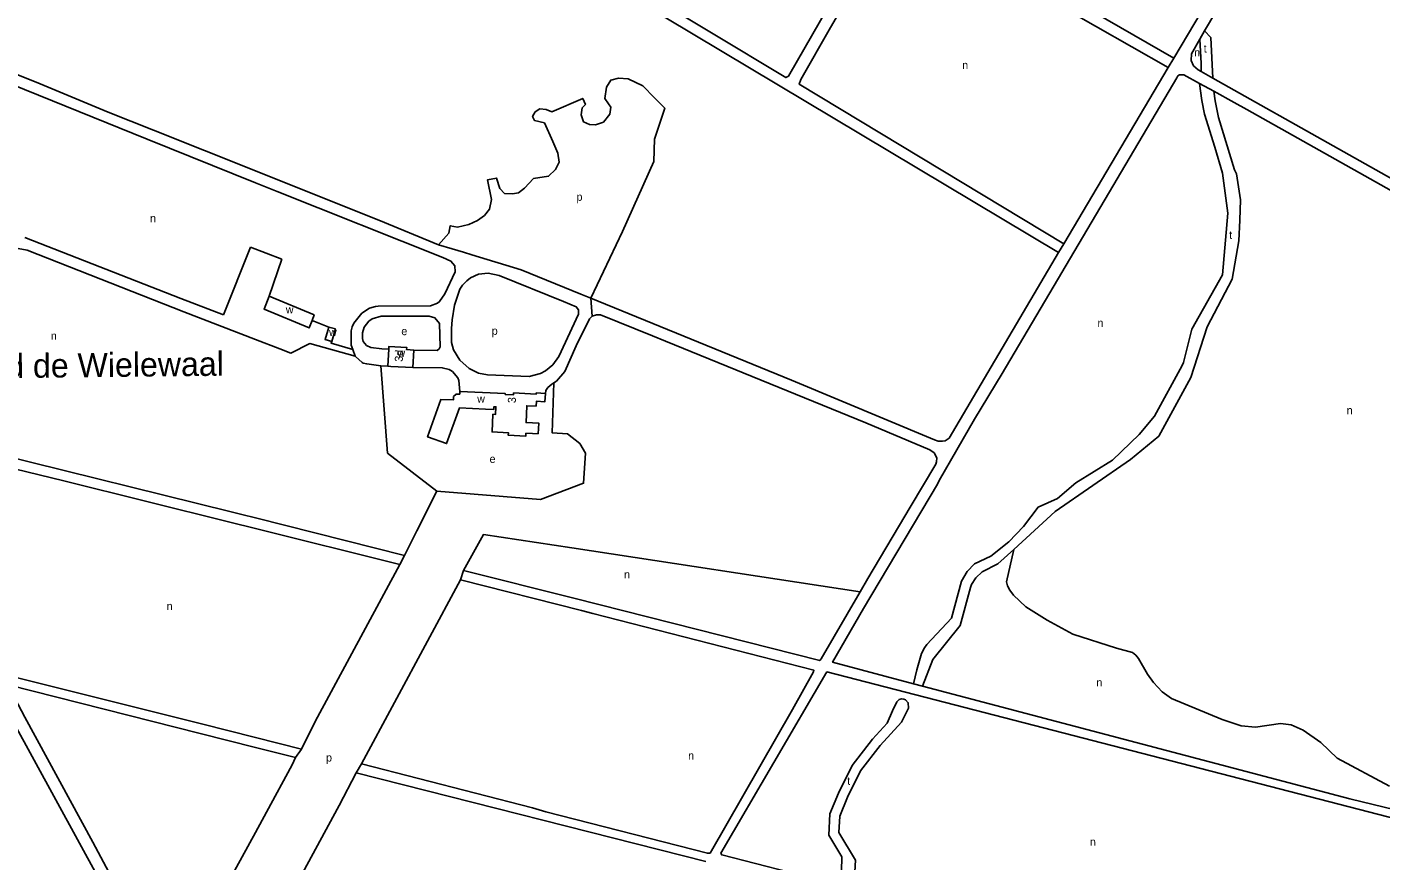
# Model space of a CAD drawing. Extents: x 156521 to 159067, y 384230 to 386095.
# Drawn here: x 157936 to 158613, y 384783 to 385200 of the extents above; entities that cross this region are included whole.
import ezdxf

# ---------------------------------------------------------------- set-up
doc = ezdxf.new("R2010")
doc.units = 0
for name, color, linetype in [('BLT_Basislijn', 7, 'Continuous'), ('BLT_Bebouwing', 7, 'Continuous'), ('BLT_Centroide', 7, 'Continuous'), ('BLT_Huisnummer', 7, 'Continuous'), ('BLT_Sport_parknaam', 7, 'Continuous'), ('BLT_Vlakafsluiter', 7, 'Continuous')]:
    doc.layers.add(name, color=color, linetype=linetype)

msp = doc.modelspace()

# ---------------------------------------------------------------- linework, layer by layer
at = {"layer": 'BLT_Basislijn'}
for p, q in [((158522.1, 385194.19), (158524.55, 385198.42)), ((158509.19, 385184.74), (158506.33, 385179.97)), ((158454.18, 385091.87), (158506.33, 385179.97)), ((158522.78, 385177.99), (158528.66, 385174.61)), ((158521.94, 385172.02), (158529.18, 385168.2)), ((158539.39, 385162.51), (158529.18, 385168.2)), ((158034.03, 385056.38), (158047.49, 385090.13)), ((158047.49, 385090.13), (158063.22, 385084.15)), ((158148.42, 385089.36), (158141.58, 385091.37)), ((158154.01, 385087.61), (158148.42, 385089.36)), ((158454.18, 385091.87), (158451.58, 385087.55)), ((158063.22, 385084.15), (158056.81, 385065.74)), ((158154.01, 385087.61), (158158.2, 385086.34)), ((158012.65, 385064.54), (158034.03, 385056.38)), ((158212.75, 385066.62), (158217.64, 385064.67)), ((158078.31, 385053.48), (158086.67, 385050.25)), ((158098.71, 385038.98), (158099.91, 385035.72)), ((158113.23, 385039.37), (158116.63, 385039.17)), ((158112.74, 385030.84), (158116.14, 385030.64)), ((157852.35, 385003.63), (158037.88, 384957.79)), ((158037.88, 384957.79), (158043.15, 384956.48)), ((158050, 384954.76), (158043.15, 384956.48)), ((158124.62, 384936.05), (158050, 384954.76)), ((158122.2, 384931.55), (158050, 384949.5)), ((158122.2, 384931.55), (158124.62, 384936.05)), ((158154.07, 384928.52), (158152.46, 384923.86)), ((158209.27, 384914.6), (158154.07, 384928.52)), ((158152.46, 384923.86), (158103.09, 384831.78)), ((158152.46, 384923.86), (158213.1, 384908.5)), ((157924.31, 384876.54), (158022.99, 384851.73)), ((158383.51, 384870.65), (158379.02, 384871.85)), ((158022.99, 384851.73), (158050, 384844.94)), ((158050, 384844.94), (158073, 384839.16)), ((158050, 384840.02), (158070.12, 384834.92)), ((158070.12, 384834.92), (158073, 384839.16)), ((158103.09, 384831.78), (158100.39, 384827.29)), ((158188.54, 384809.83), (158103.09, 384831.78)), ((158100.39, 384827.29), (158275.16, 384782.89))]:
    msp.add_line(p, q, dxfattribs=at)
for points in [[(158182.12, 385374.2), (158291.65, 385310.46), (158371.52, 385264.04), (158509.19, 385184.74)], [(157976.34, 385157.64), (157942.43, 385171.89), (157884.65, 385195.02), (157881.29, 385197.34), (157879.08, 385199.55), (157877.9, 385202.27), (157877.79, 385205.87), (157879.29, 385210.09), (157933.78, 385294.51), (157934.28, 385295.7), (157981.19, 385369.95)], [(158549.58, 385278.11), (158551.86, 385261.78), (158551.57, 385256.78), (158551.09, 385255.51), (158509.19, 385184.74)], [(158524.55, 385198.42), (158554.77, 385249.34), (158558.89, 385253.82), (158563, 385256.41), (158566.95, 385258.07), (158588.51, 385261.81)], [(158454.18, 385091.87), (158321.77, 385171.77), (158322.73, 385173.94), (158337.59, 385199.98), (158370.85, 385257.22), (158379.91, 385252.58), (158433.65, 385221.48), (158506.33, 385179.97)], [(158203.7, 385242.18), (158315.18, 385175.02), (158316.51, 385175.77), (158336.27, 385210.21), (158342.84, 385221.87)], [(158451.58, 385087.55), (158212.45, 385230.51), (158202.32, 385236.66)], [(158528.66, 385174.61), (158527.61, 385194.95), (158524.55, 385198.42)], [(157831.84, 385134.63), (157861.46, 385181.39), (157866.33, 385188.34), (157869.88, 385190.77), (157872.04, 385191.4), (157876.54, 385191.85), (157880.01, 385191.02), (157995.96, 385144.13)], [(158522.1, 385194.19), (158517.98, 385186.9), (158517.82, 385183.49), (158519.08, 385180.87), (158521.36, 385178.8), (158522.78, 385177.99)], [(158522.1, 385194.19), (158522.85, 385182), (158522.78, 385177.99)], [(158141.58, 385091.37), (158146.67, 385097.18), (158147.38, 385100.91), (158151.11, 385100.19), (158156.65, 385101.54), (158161.06, 385103.45), (158164.46, 385106.03), (158167.04, 385109.13), (158168.05, 385114.07), (158166.11, 385123.87), (158170.61, 385124.76), (158172.27, 385119.53), (158174.55, 385117.06), (158178.47, 385116.84), (158181.57, 385117.4), (158184.49, 385119.64), (158189.05, 385124.46), (158196.56, 385125.61), (158200, 385128.97), (158201.87, 385132.6), (158201.27, 385137.2), (158198.62, 385143.1), (158194.49, 385152.29), (158189.57, 385153.5), (158188.56, 385155.52), (158189.83, 385157.8), (158192.26, 385159.41), (158195.32, 385159.07), (158198.12, 385157.8), (158213.67, 385164.56), (158215.01, 385161.5), (158213.34, 385159.85), (158212.89, 385156.42), (158214.05, 385152.9), (158217.07, 385151.56), (158220.1, 385151.41), (158223.95, 385152.68), (158227.16, 385156.67), (158227.72, 385160.19), (158226.56, 385161.83), (158224.73, 385164.44), (158225.59, 385170.13), (158227.75, 385173.73), (158231.47, 385174.71), (158236.31, 385174.38), (158243.63, 385170.85), (158249.52, 385164.9), (158254.63, 385159.73), (158249.5, 385144.19), (158249.24, 385132.94), (158233.53, 385098.01), (158217.64, 385064.67)], [(158521.94, 385172.02), (158514.16, 385176.39), (158512, 385176.39), (158511.18, 385175.79), (158510.6, 385174.89), (158423.37, 385027.06), (158409.56, 385004.11), (158391.81, 384973.56), (158390.96, 384971.68), (158354.04, 384909.41), (158338.53, 384882.65), (158379.02, 384871.85)], [(158521.94, 385172.02), (158523.15, 385163.55), (158524.51, 385156.68), (158529.74, 385140.21), (158533.42, 385127.14), (158536.18, 385107.11), (158533.42, 385076.42), (158518.14, 385049.14), (158514.07, 385032.58), (158513.4, 385030.92), (158499.49, 385005.64), (158491.83, 384996.53), (158478.44, 384983.62), (158460.1, 384972.35), (158451.06, 384964.55), (158441.32, 384960.12), (158433.93, 384950.54), (158426.68, 384942.9), (158417.7, 384935.58), (158409.58, 384931.78), (158405.85, 384928.03), (158403.05, 384923.07), (158397.96, 384904.62), (158385.72, 384891.51), (158384.5, 384889.88), (158383.06, 384887.03), (158380.64, 384878.87), (158379.02, 384871.85)], [(158528.66, 385174.61), (158654.35, 385103.98), (158711.3, 385071.58), (158715.21, 385069.61), (158765.14, 385040.3)], [(158540.53, 385126.81), (158539.56, 385128.87), (158531.51, 385155), (158529.83, 385163.43), (158529.18, 385168.2)], [(158050, 385128.33), (157999.1, 385148.7), (157976.34, 385157.64)], [(158539.39, 385162.51), (158545.74, 385158.98), (158651.48, 385099.52), (158683.59, 385080.92)], [(157995.96, 385144.13), (158050, 385122.29)], [(158066.21, 385121.84), (158050, 385128.33)], [(158540.53, 385126.81), (158542.54, 385113.77), (158542.14, 385103.72), (158541.65, 385093.39), (158538.36, 385074.23), (158525.83, 385050.35), (158517.67, 385024.94), (158501.72, 384995.72), (158487.57, 384983.96), (158449.92, 384957.93), (158429.1, 384938.99)], [(158050, 385122.29), (158060.9, 385117.95)], [(158060.9, 385117.95), (158143.68, 385085.05), (158147.77, 385083.13), (158149.63, 385080.82), (158149.79, 385077.89), (158144.7, 385066.81), (158142.09, 385062.99), (158141.05, 385062.11), (158137.6, 385060.92), (158111.41, 385060.68), (158110.06, 385060.44), (158106.97, 385059.65), (158103.14, 385057.15), (158099.29, 385052.09)], [(158141.58, 385091.37), (158111.78, 385103.6), (158066.21, 385121.84)], [(157812.16, 385103.68), (157877.05, 385099.58), (157935.85, 385088.63)], [(157934.68, 385094.95), (158012.65, 385064.54)], [(157935.85, 385088.63), (158014.22, 385057.9)], [(158158.2, 385086.34), (158182.9, 385078.84), (158212.75, 385066.62)], [(158217.64, 385064.67), (158318.04, 385023.68), (158389.58, 384993.77), (158391.27, 384993.11), (158393.57, 384993.17), (158394.77, 384993.33), (158396.78, 384994.7), (158451.58, 385087.55)], [(158203.95, 385063.03), (158210.44, 385060.28), (158211.49, 385058.79), (158211.5, 385056.7), (158201.68, 385035.44), (158198.66, 385031.31), (158194.96, 385028.29), (158192.61, 385026.95), (158186.82, 385025.58), (158165.96, 385026.38), (158161.48, 385027.17), (158156.84, 385029.48), (158152.13, 385033.64), (158148.99, 385038.89), (158148.07, 385042.57), (158148.04, 385049.46), (158148.43, 385053.83), (158149.58, 385061.13), (158152.18, 385069.13), (158153.61, 385071.2), (158155.68, 385073.41), (158157.52, 385074.79), (158161.57, 385076.73), (158166.35, 385077.24), (158171.92, 385075.98), (158203.95, 385063.03)], [(158014.22, 385057.9), (158050, 385044.01)], [(158129.25, 385038.72), (158140.82, 385038.43), (158141.81, 385039.38), (158142.31, 385040.38), (158141.99, 385052), (158139.76, 385054.76), (158136.9, 385055.59), (158112.86, 385055.59), (158108.31, 385054.33), (158106.72, 385053.12), (158104.42, 385050.19), (158103.51, 385047.42), (158103.51, 385044.46), (158103.95, 385042.92), (158105.6, 385040.93), (158107.77, 385040.07), (158113.23, 385039.37)], [(158199.28, 385022.35), (158200.51, 385023.19), (158204.71, 385027.96), (158210.29, 385040.84), (158216.97, 385054.39), (158218.34, 385055.73)], [(158218.34, 385055.73), (158220.53, 385056.28), (158222.54, 385056.3), (158248.53, 385045.78), (158254.98, 385043.14), (158355.12, 385002.33), (158387.23, 384988.9), (158389.3, 384987.4), (158390.73, 384984.77), (158390.55, 384982.84), (158390.13, 384981.63), (158377.39, 384960.15), (158374.72, 384955.66), (158356.25, 384924.52), (158352.4, 384917.74)], [(158099.29, 385052.09), (158098.39, 385050.39), (158097.85, 385048.28), (158097.9, 385041.18), (158098.71, 385038.98)], [(158050, 385044.01), (158062.29, 385039.28)], [(158062.29, 385039.28), (158067.72, 385037.1), (158077.13, 385041.96), (158099.91, 385035.72)], [(158088.14, 385043.06), (158087.87, 385042.14), (158098.71, 385038.98)], [(158099.91, 385035.72), (158100.01, 385035.46), (158103.35, 385032.43), (158103.95, 385032.19)], [(158103.95, 385032.19), (158105.63, 385031.81), (158112.74, 385030.84)], [(158140.74, 384968.09), (158116.03, 384987.18), (158112.74, 385030.84)], [(158152.23, 385017.97), (158151.7, 385023.51), (158151.22, 385024.78), (158148.52, 385028.04), (158146.9, 385028.97), (158143.43, 385029.89), (158128.75, 385030.06)], [(158140.74, 384968.09), (158192.58, 384963.99), (158214.11, 384972.11), (158215.11, 384987.15), (158212.12, 384991.97), (158206.06, 384996.76), (158198.35, 384997.33), (158198.54, 385002.41), (158199.28, 385022.35)], [(158199.28, 385022.35), (158198.15, 385021.75), (158196.22, 385020.05), (158195.18, 385018.56), (158194.97, 385017.04)], [(158037.16, 384952.69), (157954.15, 384973.32), (157856.66, 384997.07)], [(158124.62, 384936.05), (158130.75, 384948.31), (158140.74, 384968.09)], [(158050, 384949.5), (158037.16, 384952.69)], [(158352.4, 384917.74), (158208.13, 384939.84), (158164.03, 384946.46), (158154.07, 384928.52)], [(158429.1, 384938.99), (158421.21, 384931.81), (158413.4, 384927.74), (158410.22, 384924.82), (158408.08, 384921.54), (158407.45, 384919.95), (158402.42, 384901.03), (158388.61, 384884.03), (158383.51, 384870.65)], [(158616.96, 384820.59), (158590.84, 384834.71), (158582.67, 384842.46), (158573.84, 384848.58), (158567.75, 384851.26), (158562.46, 384851.9), (158550.04, 384850.21), (158542.81, 384850.88), (158533.25, 384854.01), (158507.99, 384864.54), (158503.35, 384867.76), (158499.07, 384872.55), (158496.03, 384876.62), (158491.57, 384884.43), (158490.12, 384886.18), (158488.44, 384887.48), (158480.5, 384889.63), (158458.64, 384896.61), (158445.81, 384903.57), (158435.16, 384910.27), (158429, 384916.2), (158427.21, 384918.64), (158425.97, 384920.74), (158425.44, 384922.74), (158429.1, 384938.99)], [(158073, 384839.16), (158079.95, 384852.93), (158122.2, 384931.55)], [(158352.4, 384917.74), (158332.87, 384884.25), (158332.15, 384883.46), (158209.27, 384914.6)], [(158188.54, 384809.83), (158195.14, 384807.87), (158276.02, 384787.12), (158277.3, 384787.09), (158318.58, 384859.01), (158329.03, 384877.79), (158329.19, 384878.59), (158218.67, 384906.96), (158213.1, 384908.5)], [(157995.65, 384730.34), (157982.71, 384754.25), (157917.51, 384873.23), (157868.18, 384885.68), (157845.99, 384890.93)], [(158342.81, 384770.73), (158333.64, 384773.36), (158283.17, 384786.22), (158282.77, 384787.06), (158335.72, 384877.79), (158631, 384801.39), (158631.05, 384800.83), (158627.73, 384794.49), (158603.23, 384753.88), (158602.28, 384751.89), (158580.79, 384715.97), (158576.88, 384709.55), (158576.56, 384709.5), (158462.13, 384739.64), (158349.17, 384768.98)], [(158000.94, 384733.19), (157997.78, 384738.29), (157968.8, 384792.69), (157934.68, 384855.1), (157926.36, 384870.92), (157926.44, 384871.29), (158022.33, 384847.02)], [(158625.27, 384807.42), (158597.16, 384814.34), (158383.51, 384870.65)], [(158365.9, 384852.2), (158368.52, 384858.35), (158370.73, 384862.8), (158371.79, 384863.91), (158373.06, 384864.28), (158374.25, 384864.19), (158374.99, 384863.89), (158376.37, 384862.32), (158376.47, 384859.71), (158373.09, 384852.64)], [(158365.9, 384852.2), (158358.55, 384844.17), (158348.33, 384831.03), (158341.47, 384817.14), (158337.14, 384806.78), (158336.69, 384796.16), (158343.14, 384785.29)], [(158373.09, 384852.64), (158362.37, 384840.94), (158352.58, 384828.36), (158346.02, 384815.07), (158342.1, 384805.67), (158341.75, 384797.43), (158349.95, 384783.61)], [(158022.33, 384847.02), (158050, 384840.02)], [(158017.25, 384735.99), (158018.55, 384739.35), (158026.59, 384754.11), (158027.24, 384755.78), (158050, 384797.52), (158055.51, 384807.62), (158068.42, 384831.28), (158070.12, 384834.92)], [(158100.39, 384827.29), (158091.95, 384810.99), (158066.98, 384765.07), (158050, 384733.85), (158043.28, 384721.5)], [(158342.81, 384770.73), (158343.14, 384785.29)], [(158349.95, 384783.61), (158349.17, 384768.98)]]:
    msp.add_lwpolyline(points, dxfattribs=at)
at = {"layer": 'BLT_Bebouwing'}
for p, q in [((158116.63, 385039.17), (158116.14, 385030.64)), ((158128.75, 385030.06), (158129.25, 385038.72)), ((158188.55, 384997.01), (158185.27, 384997.16)), ((158191.42, 384996.88), (158188.55, 384997.01))]:
    msp.add_line(p, q, dxfattribs=at)
for points in [[(158056.81, 385065.74), (158054.33, 385059.22), (158076.88, 385049.78), (158078.31, 385053.48)], [(158078.31, 385053.48), (158079.36, 385056.3), (158056.81, 385065.74)], [(158086.67, 385050.25), (158084.85, 385044.03), (158088.14, 385043.06)], [(158088.14, 385043.06), (158089.96, 385049.28), (158086.67, 385050.25)], [(158129.25, 385038.72), (158125.61, 385038.93), (158125.68, 385040.02), (158116.71, 385040.53), (158116.63, 385039.17)], [(158116.14, 385030.64), (158117.66, 385030.55), (158128.75, 385030.06)], [(158150.4, 385016.74), (158149.05, 385015.48), (158148.97, 385013.78), (158142.71, 385014.04), (158136.07, 384995.32), (158145.57, 384991.92), (158151.97, 385009.79), (158164.97, 385009.2), (158169.21, 385009.08), (158169.27, 385010.38), (158170.27, 385010.34), (158170.1, 385006.53), (158168.73, 385006.59), (158168.32, 384997.76), (158176.46, 384997.39), (158176.4, 384996.11), (158185.21, 384995.71), (158185.27, 384997.16)], [(158152.23, 385017.97), (158152.15, 385016.68), (158150.4, 385016.74)], [(158179, 385017.25), (158178.96, 385016.32), (158174.88, 385016.54), (158174.9, 385016.94), (158174.9, 385016.94), (158152.23, 385017.97)], [(158194.97, 385017.04), (158190.41, 385017.25), (158190.4, 385016.71), (158179, 385017.25)], [(158194.97, 385017.04), (158194.78, 385012.9), (158190.51, 385013.09), (158190.4, 385010.69)], [(158190.4, 385010.69), (158185.67, 385010.9), (158185.29, 385002.48), (158191.66, 385002.19), (158191.42, 384996.88)]]:
    msp.add_lwpolyline(points, dxfattribs=at)
at = {"layer": 'BLT_Vlakafsluiter'}
msp.add_line((158217.64, 385064.67), (158218.34, 385055.73), dxfattribs=at)

# ---------------------------------------------------------------- texts
at = {"layer": 'BLT_Centroide'}
for s, p in [('t', (158524.09, 385187.5)), ('n', (158519.33, 385185.56)), ('n', (158403.37, 385179.25)), ('p', (158210.53, 385113.35)), ('n', (157997.32, 385102.65)), ('t', (158536.82, 385094.3)), ('w', (158065.19, 385057.02)), ('w', (158086.8, 385045.76)), ('e', (158122.95, 385046.18)), ('p', (158168.16, 385046.34)), ('n', (158470.99, 385050.29)), ('n', (157947.72, 385043.85)), ('w', (158121.02, 385035.31)), ('w', (158160.88, 385012.39)), ('n', (158595.6, 385006.6)), ('e', (158167.07, 384982.29)), ('n', (158234.32, 384924.5)), ('n', (158005.63, 384908.7)), ('n', (158470.43, 384870.52)), ('p', (158085.32, 384832.95)), ('n', (158266.34, 384833.93)), ('t', (158345.89, 384821.29)), ('n', (158467.21, 384790.82))]:
    msp.add_text(s, height=4, dxfattribs=at).set_placement(p)
at = {"layer": 'BLT_Huisnummer'}
for s, rotation, p in [('3d', 86.70917, (158123.61, 385032.75)), ('3', 88.23506, (158180.18, 385012.14))]:
    msp.add_text(s, height=4, rotation=rotation, dxfattribs=at).set_placement(p)
at = {"layer": 'BLT_Sport_parknaam'}
msp.add_text('Landgoed de Wielewaal', height=12, rotation=0.63481, dxfattribs=at).set_placement((157863, 385024.01))

doc.saveas('drawing.dxf')
